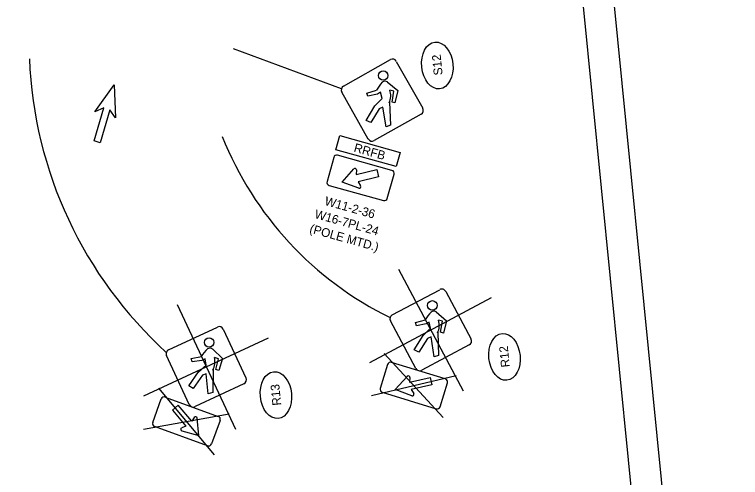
# Model space of a CAD drawing. Extents: x 2210919 to 2211172, y 637144 to 637504.
# Drawn here: x 2211055.9 to 2211171.8, y 637293.5 to 637367.4 of the extents above; entities that cross this region are included whole.
import ezdxf

# ---------------------------------------------------------------- set-up
doc = ezdxf.new("R2010")
doc.units = 0
for name, color, linetype in [('PM_P_Cells', 7, 'Continuous'), ('SH_Border', 7, 'Continuous'), ('SH_Cut_Line', 7, 'Continuous'), ('SH_Text', 7, 'Continuous'), ('SN_P_Signs', 7, 'Continuous'), ('SN_P_Text', 7, 'Continuous'), ('SN_X_Public', 7, 'Continuous'), ('SN_X_Text', 7, 'Continuous')]:
    doc.layers.add(name, color=color, linetype=linetype)

msp = doc.modelspace()

# ---------------------------------------------------------------- linework, layer by layer
at = {"layer": 'PM_P_Cells'}
for p, q in [((2211068.67, 637351.89), (2211071.76, 637356.18)), ((2211071.76, 637356.18), (2211071.76, 637356.18)), ((2211071.76, 637356.18), (2211071.99, 637350.89)), ((2211068.56, 637347.22), (2211070.14, 637352.49)), ((2211070.14, 637352.49), (2211068.67, 637351.89)), ((2211071.09, 637352.2), (2211069.52, 637346.93)), ((2211071.99, 637350.89), (2211071.09, 637352.2)), ((2211069.52, 637346.93), (2211068.56, 637347.22)), ((2211069.04, 637347.08), (2211069.04, 637347.08))]:
    msp.add_line(p, q, dxfattribs=at)
at = {"layer": 'SH_Border'}
msp.add_lwpolyline([(2210956.37, 637159.81), (2210924.77, 637478.24), (2211133.74, 637498.98), (2211165.34, 637180.55)], close=True, dxfattribs=at)
at = {"layer": 'SH_Cut_Line'}
msp.add_lwpolyline([(2211171.8, 637166.11), (2211138.22, 637504.45), (2210919.3, 637482.73), (2210952.88, 637144.39)], close=True, dxfattribs=at)
at = {"layer": 'SH_Text'}
for p, q in [((2211108.06, 637355.56), (2211090.82, 637361.93)), ((2211110.44, 637341.85), (2211113.7, 637342.68)), ((2211110.48, 637342.59), (2211110.44, 637341.85)), ((2211113.7, 637342.68), (2211114, 637341.51)), ((2211114, 637341.51), (2211110.74, 637340.67)), ((2211110.74, 637340.67), (2211111.14, 637340.04)), ((2211110.85, 637339.68), (2211110.85, 637339.68))]:
    msp.add_line(p, q, dxfattribs=at)
msp.add_lwpolyline([(2211107.82, 637348.07), (2211117.45, 637345.38), (2211116.82, 637343.13), (2211107.19, 637345.82)], close=True, dxfattribs=at)
for points in [[(2211116.13, 637342.52), (2211107.46, 637344.94)], [(2211106.85, 637344.59), (2211105.77, 637340.74)], [(2211110.85, 637339.68), (2211108.2, 637340.64), (2211110.06, 637342.76)], [(2211115.4, 637338.05), (2211116.48, 637341.9)], [(2211106.12, 637340.13), (2211114.79, 637337.7)]]:
    msp.add_lwpolyline(points, dxfattribs=at)
for centre, radius, start, end in [((2211107.33, 637344.46), 0.5, 74.3891, 164.3891), ((2211110.24, 637342.6), 0.243, 356.5762, 138.7128), ((2211116, 637342.04), 0.5, 344.3891, 74.3891), ((2211106.25, 637340.61), 0.5, 164.3891, 254.3891), ((2211110.93, 637339.91), 0.243, 250.0654, 32.2019), ((2211114.92, 637338.19), 0.5, 254.3891, 344.3891)]:
    msp.add_arc(centre, radius, start, end, dxfattribs=at)
for centre in [(2211123.38, 637359.27), (2211134.11, 637312.75), (2211097.61, 637306.65)]:
    msp.add_ellipse(centre, major_axis=(-0.37, 3.73), ratio=0.666667, dxfattribs=at)
at = {"layer": 'SN_P_Signs'}
for p, q in [((2211115.4, 637356.65), (2211117.08, 637355.28)), ((2211112.13, 637354.85), (2211113.69, 637355.32)), ((2211116.43, 637355.16), (2211115.8, 637355.33)), ((2211112.29, 637354.35), (2211112.13, 637354.85)), ((2211113.82, 637354.68), (2211112.29, 637354.35)), ((2211114.32, 637354.99), (2211113.82, 637354.68)), ((2211114.57, 637354.02), (2211114.32, 637354.99)), ((2211116.15, 637353.42), (2211116.43, 637355.16)), ((2211117.08, 637355.28), (2211116.62, 637353.29)), ((2211113.41, 637352.83), (2211114.57, 637354.02)), ((2211115.73, 637353.39), (2211115.93, 637349.72)), ((2211116.62, 637353.29), (2211116.15, 637353.42)), ((2211112.04, 637350.5), (2211113.41, 637352.83)), ((2211114.1, 637352.34), (2211112.77, 637350.15)), ((2211114.69, 637352.63), (2211114.1, 637352.34)), ((2211115.24, 637349.46), (2211114.69, 637352.63)), ((2211112.77, 637350.15), (2211112.04, 637350.5)), ((2211115.93, 637349.72), (2211115.24, 637349.46))]:
    msp.add_line(p, q, dxfattribs=at)
for points in [[(2211108.39, 637355.98), (2211115.89, 637360.2)], [(2211116.84, 637359.93), (2211121.06, 637352.44)], [(2211112.35, 637347.53), (2211108.13, 637355.03)], [(2211120.79, 637351.49), (2211113.3, 637347.27)]]:
    msp.add_lwpolyline(points, dxfattribs=at)
msp.add_circle((2211114.75, 637357.66), 0.758, dxfattribs=at)
for centre, radius, start, end in [((2211116.23, 637359.59), 0.7, 29.3891, 119.3891), ((2211118.07, 637353.22), 4.85, 135.9302, 154.4207), ((2211115.04, 637355.99), 0.751, 60.6332, 126.8841), ((2211108.74, 637355.37), 0.7, 119.3891, 209.3891), ((2211113.12, 637354.44), 2.82, 336.2392, 18.45), ((2211120.45, 637352.1), 0.7, 299.3891, 29.3891), ((2211112.96, 637347.88), 0.7, 209.3891, 299.3891)]:
    msp.add_arc(centre, radius, start, end, dxfattribs=at)
at = {"layer": 'SN_X_Public'}
for p, q in [((2211117.17, 637326.77), (2211127.5, 637307.33)), ((2211112.62, 637311.88), (2211132.05, 637322.22)), ((2211081.82, 637321.14), (2211091.14, 637301.2)), ((2211123.21, 637319.94), (2211124.85, 637318.53)), ((2211119.9, 637318.23), (2211121.48, 637318.65)), ((2211120.05, 637317.72), (2211119.9, 637318.23)), ((2211122.1, 637318.31), (2211121.59, 637318.01)), ((2211122.31, 637317.33), (2211122.1, 637318.31)), ((2211124.2, 637318.43), (2211123.58, 637318.62)), ((2211123.88, 637316.7), (2211124.2, 637318.43)), ((2211124.85, 637318.53), (2211124.35, 637316.56)), ((2211121.59, 637318.01), (2211120.05, 637317.72)), ((2211121.13, 637316.18), (2211122.31, 637317.33)), ((2211119.71, 637313.88), (2211121.13, 637316.18)), ((2211122.41, 637315.94), (2211121.81, 637315.67)), ((2211122.88, 637312.76), (2211122.41, 637315.94)), ((2211123.46, 637316.68), (2211123.58, 637313)), ((2211124.35, 637316.56), (2211123.88, 637316.7)), ((2211076.51, 637306.51), (2211096.45, 637315.82)), ((2211121.81, 637315.67), (2211120.42, 637313.51)), ((2211087.51, 637314.01), (2211089.07, 637312.52)), ((2211120.42, 637313.51), (2211119.71, 637313.88)), ((2211084.1, 637312.47), (2211085.7, 637312.81)), ((2211084.23, 637311.95), (2211084.1, 637312.47)), ((2211086.31, 637312.44), (2211085.78, 637312.16)), ((2211086.47, 637311.45), (2211086.31, 637312.44)), ((2211088.42, 637312.45), (2211087.8, 637312.67)), ((2211088.01, 637310.74), (2211088.42, 637312.45)), ((2211089.07, 637312.52), (2211088.47, 637310.57)), ((2211114.91, 637313.27), (2211124.34, 637303.07)), ((2211123.58, 637313), (2211122.88, 637312.76)), ((2211085.78, 637312.16), (2211084.23, 637311.95)), ((2211085.23, 637310.36), (2211086.47, 637311.45)), ((2211083.69, 637308.14), (2211085.23, 637310.36)), ((2211087.58, 637310.74), (2211087.51, 637307.06)), ((2211088.47, 637310.57), (2211088.01, 637310.74)), ((2211085.88, 637309.81), (2211084.39, 637307.73)), ((2211086.49, 637310.05), (2211085.88, 637309.81)), ((2211086.8, 637306.85), (2211086.49, 637310.05)), ((2211112.86, 637306.58), (2211126.39, 637309.77)), ((2211118.95, 637308.71), (2211122.23, 637309.47)), ((2211119.01, 637309.45), (2211118.95, 637308.71)), ((2211122.23, 637309.47), (2211122.5, 637308.29)), ((2211078.87, 637307.78), (2211087.76, 637297.1)), ((2211084.39, 637307.73), (2211083.69, 637308.14)), ((2211122.5, 637308.29), (2211119.23, 637307.53)), ((2211087.51, 637307.06), (2211086.8, 637306.85)), ((2211119.23, 637307.53), (2211119.61, 637306.89)), ((2211119.31, 637306.54), (2211119.31, 637306.54)), ((2211082.01, 637305.05), (2211081.08, 637304.26)), ((2211084.18, 637302.47), (2211082.01, 637305.05)), ((2211076.48, 637301.2), (2211090.15, 637303.68)), ((2211081.08, 637304.26), (2211083.25, 637301.69)), ((2211084.57, 637303.1), (2211084.18, 637302.47)), ((2211083.25, 637301.69), (2211082.56, 637301.41)), ((2211082.59, 637300.95), (2211082.58, 637300.95))]:
    msp.add_line(p, q, dxfattribs=at)
for points in [[(2211116.19, 637319.44), (2211123.78, 637323.48)], [(2211124.73, 637323.19), (2211128.77, 637315.6)], [(2211119.94, 637310.91), (2211115.9, 637318.5)], [(2211080.47, 637313.88), (2211088.26, 637317.52)], [(2211089.19, 637317.18), (2211092.83, 637309.39)], [(2211128.48, 637314.65), (2211120.89, 637310.62)], [(2211083.77, 637305.15), (2211080.13, 637312.95)], [(2211115.43, 637311.55), (2211114.26, 637307.72)], [(2211124.66, 637309.25), (2211116.05, 637311.88)], [(2211119.31, 637306.54), (2211116.68, 637307.57), (2211118.59, 637309.64)], [(2211092.49, 637308.46), (2211084.7, 637304.82)], [(2211123.82, 637304.8), (2211124.99, 637308.63)], [(2211114.59, 637307.1), (2211123.2, 637304.47)], [(2211077.93, 637302.27), (2211079.3, 637306.03)], [(2211079.94, 637306.33), (2211088.4, 637303.26)], [(2211082.58, 637300.95), (2211085.3, 637300.19), (2211085.02, 637302.99)], [(2211088.69, 637302.61), (2211087.33, 637298.86)], [(2211086.69, 637298.56), (2211078.23, 637301.63)]]:
    msp.add_lwpolyline(points, dxfattribs=at)
for centre in [(2211122.59, 637320.97), (2211086.94, 637315.06)]:
    msp.add_circle(centre, 0.758, dxfattribs=at)
for centre, radius, start, end in [((2211124.11, 637322.87), 0.7, 28.01, 118.01), ((2211116.52, 637318.83), 0.7, 118.01, 208.01), ((2211125.79, 637316.46), 4.85, 134.5511, 153.0417), ((2211122.83, 637319.3), 0.751, 59.2541, 125.505), ((2211120.88, 637317.79), 2.82, 334.8601, 17.0709), ((2211088.56, 637316.88), 0.7, 25.0396, 115.0396), ((2211128.15, 637315.27), 0.7, 298.01, 28.01), ((2211080.77, 637313.24), 0.7, 115.0396, 205.0396), ((2211089.9, 637310.39), 4.85, 131.5807, 150.0713), ((2211087.09, 637313.38), 0.751, 56.2838, 122.5346), ((2211085.06, 637311.98), 2.82, 331.8898, 14.1005), ((2211115.91, 637311.4), 0.5, 73.01, 163.01), ((2211120.56, 637311.23), 0.7, 208.01, 298.01), ((2211092.2, 637309.09), 0.7, 295.0396, 25.0396), ((2211118.77, 637309.47), 0.243, 355.1972, 137.3337), ((2211124.51, 637308.77), 0.5, 343.01, 73.01), ((2211114.74, 637307.58), 0.5, 163.01, 253.01), ((2211119.4, 637306.77), 0.243, 248.6863, 30.8228), ((2211079.77, 637305.86), 0.5, 70.0396, 160.0396), ((2211084.4, 637305.45), 0.7, 205.0396, 295.0396), ((2211123.34, 637304.95), 0.5, 253.01, 343.01), ((2211084.78, 637302.97), 0.243, 5.7159, 147.8524), ((2211088.23, 637302.79), 0.5, 340.0396, 70.0396), ((2211078.4, 637302.1), 0.5, 160.0396, 250.0396), ((2211082.65, 637301.18), 0.243, 112.2268, 254.3633), ((2211086.86, 637299.03), 0.5, 250.0396, 340.0396)]:
    msp.add_arc(centre, radius, start, end, dxfattribs=at)
at = {"layer": 'SN_X_Text'}
for centre, radius, start, end in [((2211125.2, 637363.06), 67.02, 182.3161, 227.7144), ((2211139.85, 637368.16), 54.68, 201.6948, 243.9627)]:
    msp.add_arc(centre, radius, start, end, dxfattribs=at)

# ---------------------------------------------------------------- texts
at = {"layer": 'SH_Text'}
for s, p in [('S12', (2211124.24, 637357.77)), ('R12', (2211134.97, 637311.15)), ('R13', (2211098.47, 637305.05))]:
    msp.add_text(s, height=1.4, rotation=95.6672, dxfattribs=at).set_placement(p)
at = {"layer": 'SN_P_Text'}
for s, p in [('RRFB', (2211109.95, 637345.54)), ('W11-2-36', (2211105.3, 637337.03)), ('W16-7PL-24', (2211103.69, 637334.94)), ('(POLE MTD.)', (2211102.88, 637332.62))]:
    msp.add_text(s, height=1.4, rotation=344.3891, dxfattribs=at).set_placement(p)

doc.saveas('drawing.dxf')
